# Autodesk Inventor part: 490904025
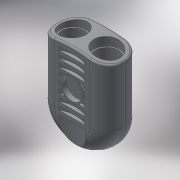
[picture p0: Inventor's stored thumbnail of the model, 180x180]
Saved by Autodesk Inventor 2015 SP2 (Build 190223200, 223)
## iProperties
Created: 2017-07
Part Number: 490904025
Material: Generic
Description: PLASSON 180° ELBOW 25
Document SubType Name: Modeling
Designer: Кирилл
Density: 1 g/cm^3
Appearance: Default
Author: Кирилл
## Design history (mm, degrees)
derived "490904.ipt"
feature "Solid1::490904.ipt"
tag "TaggingFeature1"
body "Solid1"
other parameters: "d0" = 72, "d1" = 99, "d2" = 19.8, "d3" = 7.2, "d4" = 79.2, "d5" = 43.2, "d6" = 38, "d7" = 0, "d8" = 29.7, "d9" = 29.7, "d10" = 17.1, "d11" = 1.9, "d12" = -19.8, "d13" = 15.2, "d14" = 28.8, "d15" = 29.7, "d16" = 0, "d17" = -3.96, "d18" = 3.96, "d19" = 0, "d22" = 7.92, "d23" = 25.2, "d24" = 59.4, "d26" = 0, "d27" = 21.6, "d28" = 4.75, "d29" = 0, "d30" = 0.38, "d31" = 0, "d32" = 25, "d33" = 25, "d34" = 36, "d35" = 18, "d36" = 38, "d37" = 0, "d38" = 27.5, "d39" = 27.5, "d40" = 9.5, "d41" = 0, "d42" = 22.5, "d43" = 180 deg, "d46" = 14, "d47" = 0, "d48" = 4, "d49" = 4.8, "d50" = 8, "d51" = 0, "d52" = 99, "d53" = 94.05, "d_" = 25, "L_" = 38, "L_1" = 38, "H_" = 99, "B_" = 72, "d_2" = 12
